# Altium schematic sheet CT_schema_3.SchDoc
size 293 x 134 mm
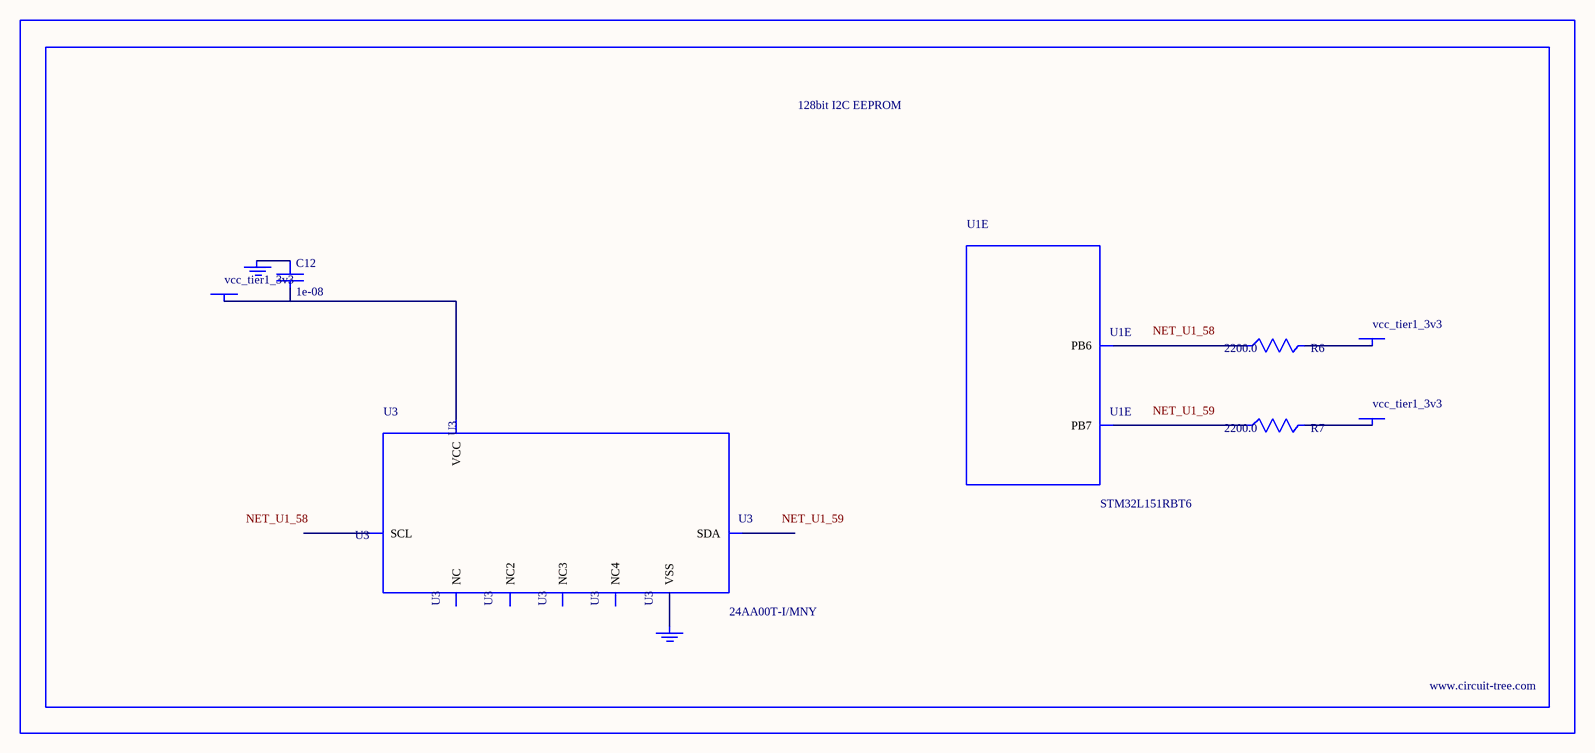
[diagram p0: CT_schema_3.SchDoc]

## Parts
BORDER2  (no value)
C12  1e-08  [C0402]
GND_INSTANCE_2_0  (no value)
GND_INSTANCE_2_1  (no value)
POWER_INSTANCE_2_0  vcc_tier1_3v3
POWER_INSTANCE_2_1  vcc_tier1_3v3
POWER_INSTANCE_2_2  vcc_tier1_3v3
R6  2200.0  [R0603]
R7  2200.0  [R0603]
U1  STM32L151RBT6  [LQFP64]  (part E of 7)
U3  24AA00T-I/MNY  [TDFN-8/6MM]

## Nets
NetC12_1: C12.1 GND_INSTANCE_2_0.0(GND)
NetC12_2: C12.2 POWER_INSTANCE_2_0.0(PWR) U3.8(VCC)
NetGND_INSTANCE_2_1_0: GND_INSTANCE_2_1.0(GND) U3.4(VSS)
NetPOWER_INSTANCE_2_1_0: POWER_INSTANCE_2_1.0(PWR) R6.2
NetPOWER_INSTANCE_2_2_0: POWER_INSTANCE_2_2.0(PWR) R7.2
NetR6_1: R6.1 U1.58(PB6)
NetR7_1: R7.1 U1.59(PB7)

Not connected (* = marked no-connect by the designer): U3 1(NC) 2(NC2) 3(NC3) 5(SDA) 6(SCL) 7(NC4)

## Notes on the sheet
- Labels drawn without touching a wire or pin: NET_U1_58, NET_U1_59

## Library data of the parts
BORDER2 = BORDER_PAGE2
C12 = C0402C103K3RAC
GND_INSTANCE_2_0 GND_INSTANCE_2_1 = GND
POWER_INSTANCE_2_0-POWER_INSTANCE_2_2 = PWR
R6 R7 = RC0603JR-072K2L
